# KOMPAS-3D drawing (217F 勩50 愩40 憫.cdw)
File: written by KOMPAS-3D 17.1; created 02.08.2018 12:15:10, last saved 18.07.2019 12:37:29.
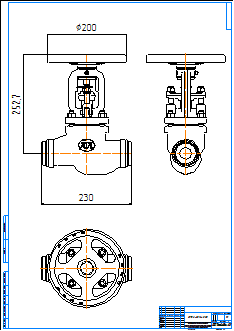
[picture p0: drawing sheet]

Sheet 1: A1, portrait

Title block, sheet 1: name: 217F Ду50 Ру40 СС; material: Внимание! Данный продукт является объектом авторского права ООО «Торговый Дом АДЛ». / Запрещается изменение, копирование, распространение / (в том числе путем копирования на другие сайты и ресурсы в Интернете) / или любое иное использование информации и объектов без предварительного / согласия правообладателя (ООО «Торговый Дом АДЛ»).; sheets: 1; organisation: ООО "Торговый дом АДЛ"; sheet format: A1; stored path: \\adlc.lan\data\АДЛ_ПКД\3D-модели\Поставщики\Zetkama\Вентили\217F\KOMPAS 2D\217F Ду50 Ру40 СС.cdw

Views: Вид 1, Проекционный вид 2, Проекционный вид 3
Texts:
  kka
  adl
Dimensions and other numbers on the sheet: 230; 252,7; 200; 1:1; 1; 217F Ду50 Ру40 СС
